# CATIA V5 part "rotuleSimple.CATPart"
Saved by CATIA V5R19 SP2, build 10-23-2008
Part number: rotuleSimple
Bounding box of the stored display mesh (mm): x -0.106 to 16.106, y -17.5 to 17.5, z -17.5 to 17.5
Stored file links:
  D:\SCHOOL\FRANCE\BANC_POUTRE_EN_MOUSSE\rotuleSimple.CATPart
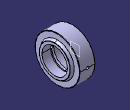
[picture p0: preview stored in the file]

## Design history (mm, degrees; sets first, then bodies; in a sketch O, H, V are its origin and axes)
Body1 "1" (main body)
  Solid1: solid without history
Body2 "2"
  Solid2: solid without history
